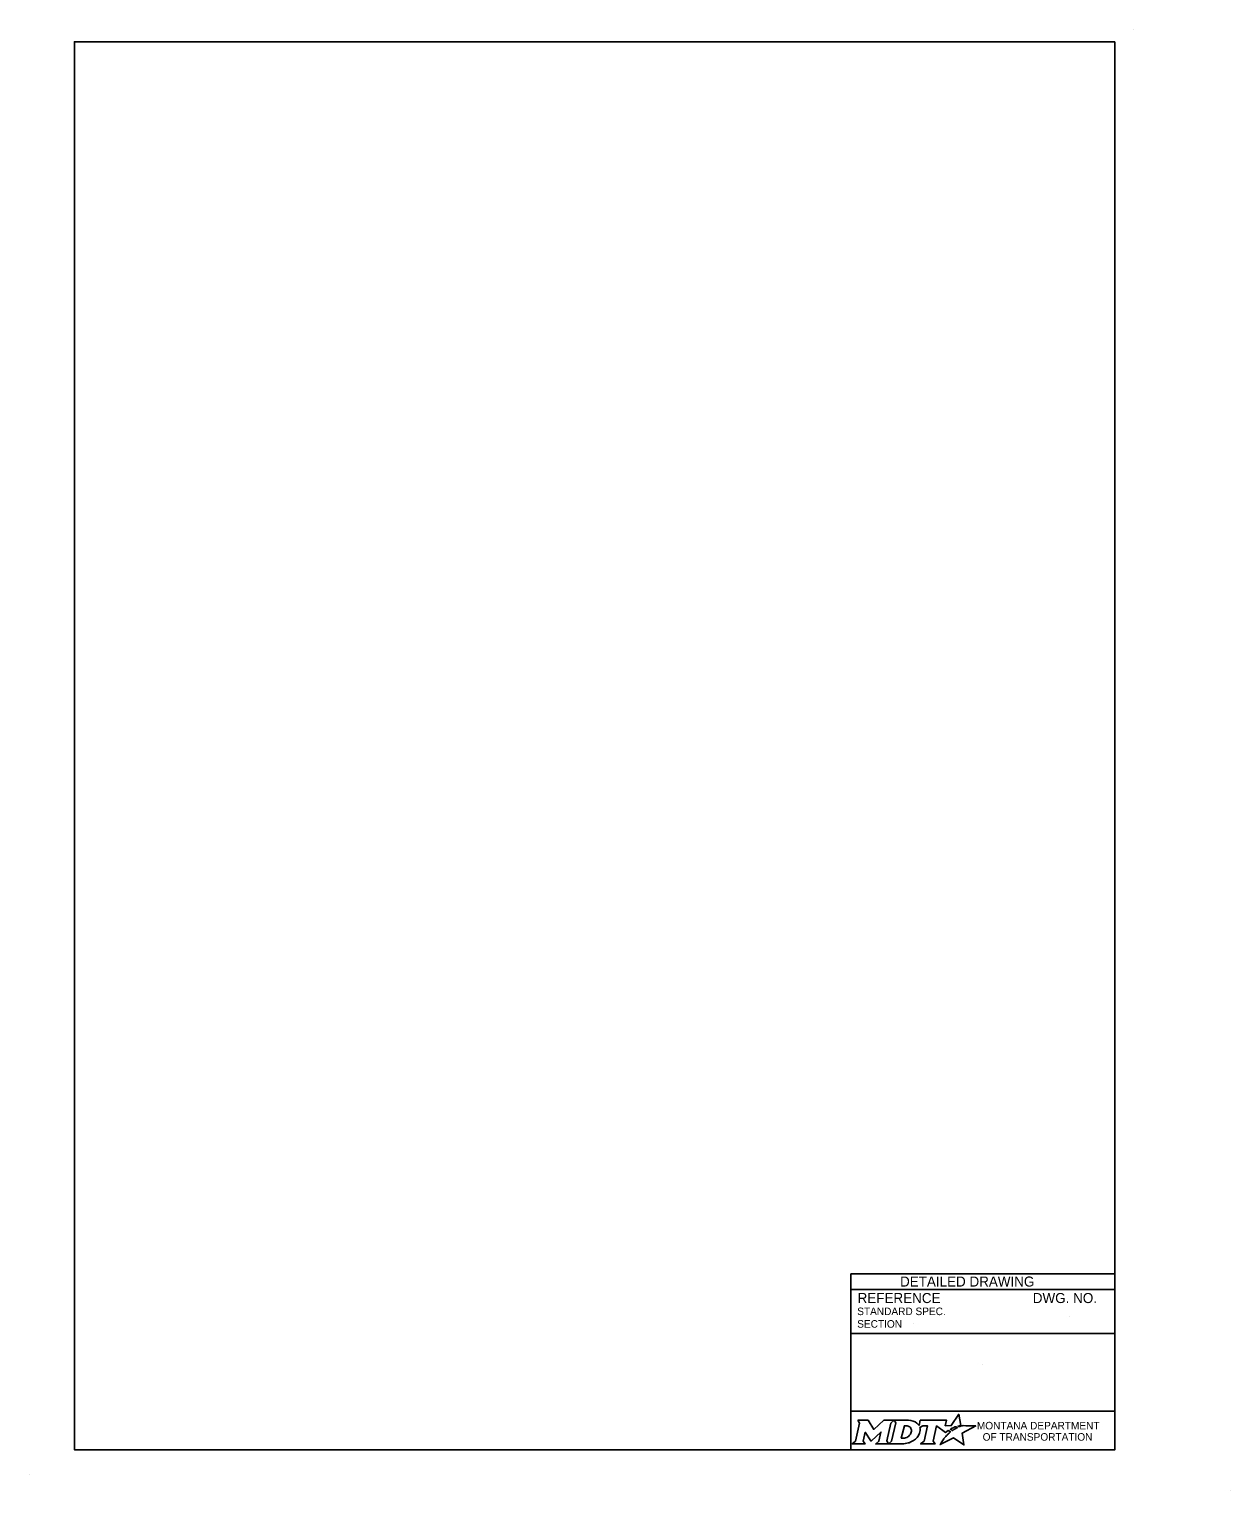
# Model space of a CAD drawing. Extents: x 49991.4 to 50021, y 49987.6 to 50011.4.
# Drawn here: x 49999.98 to 50009.54, y 49999.74 to 50011.36 of the extents above; entities that cross this region are included whole.
import ezdxf

# ---------------------------------------------------------------- set-up
doc = ezdxf.new("R2010")
doc.units = 0
doc.layers.add('Level 1', color=7, linetype='Continuous')
doc.layers.add('Level 2', color=7, linetype='Continuous')

msp = doc.modelspace()

# ---------------------------------------------------------------- linework, layer by layer
at = {"layer": 'Level 1'}
for p, q in [((50008.765, 50011.363), (50008.765, 50011.363)), ((49999.977, 49999.862), (49999.977, 49999.862)), ((50009.537, 49999.736), (50009.537, 49999.736))]:
    msp.add_line(p, q, dxfattribs=at)
msp.add_lwpolyline([(50008.615, 50011.263), (50000.336, 50011.263), (50000.336, 50000.062), (50008.615, 50000.062)], close=True, dxfattribs=at)
at = {"layer": 'Level 2'}
for p, q in [((50008.615, 50001.462), (50006.515, 50001.462)), ((50006.515, 50001.462), (50006.515, 50000.062)), ((50008.615, 50001.337), (50006.515, 50001.337)), ((50007.009, 50001.063), (50007.009, 50001.063)), ((50008.251, 50001.122), (50008.251, 50001.122)), ((50008.615, 50000.987), (50006.515, 50000.987)), ((50007.565, 50000.738), (50007.565, 50000.738)), ((50008.615, 50000.369), (50006.515, 50000.369))]:
    msp.add_line(p, q, dxfattribs=at)
for points in [[(50007.377, 50000.245), (50007.367, 50000.25), (50007.378, 50000.253), (50007.39, 50000.255), (50007.373, 50000.345), (50007.313, 50000.254), (50007.266, 50000.253), (50007.276, 50000.297), (50007.067, 50000.297), (50007.057, 50000.255), (50007.051, 50000.263)], [(50006.57, 50000.297), (50006.584, 50000.274), (50006.551, 50000.131), (50006.525, 50000.108), (50006.627, 50000.108), (50006.613, 50000.131), (50006.629, 50000.201), (50006.673, 50000.132), (50006.678, 50000.132), (50006.753, 50000.202), (50006.737, 50000.13), (50006.712, 50000.108), (50006.814, 50000.108), (50006.8, 50000.132), (50006.833, 50000.274)], [(50006.833, 50000.274), (50006.859, 50000.297), (50006.776, 50000.297), (50006.697, 50000.224), (50006.652, 50000.297), (50006.57, 50000.297)], [(50006.972, 50000.297), (50006.859, 50000.297), (50006.873, 50000.275), (50006.839, 50000.131), (50006.814, 50000.108), (50006.925, 50000.108)], [(50006.996, 50000.211), (50006.995, 50000.203), (50006.992, 50000.193), (50006.988, 50000.185), (50006.982, 50000.178), (50006.976, 50000.171), (50006.968, 50000.164), (50006.959, 50000.16), (50006.95, 50000.156), (50006.941, 50000.154), (50006.932, 50000.153), (50006.916, 50000.153), (50006.94, 50000.253), (50006.956, 50000.253), (50006.963, 50000.252), (50006.971, 50000.25), (50006.977, 50000.247), (50006.983, 50000.243), (50006.988, 50000.238), (50006.992, 50000.232), (50006.995, 50000.226), (50006.996, 50000.218), (50006.996, 50000.215), (50006.996, 50000.211)], [(50007.064, 50000.238), (50007.088, 50000.251), (50007.125, 50000.251), (50007.097, 50000.131), (50007.069, 50000.108), (50007.185, 50000.108), (50007.168, 50000.131), (50007.196, 50000.251), (50007.268, 50000.2), (50007.289, 50000.215), (50007.309, 50000.204)], [(50007.253, 50000.148), (50007.237, 50000.124), (50007.233, 50000.116), (50007.227, 50000.107), (50007.225, 50000.103), (50007.33, 50000.156), (50007.414, 50000.101), (50007.401, 50000.194), (50007.508, 50000.252), (50007.458, 50000.253), (50007.428, 50000.253), (50007.407, 50000.254), (50007.401, 50000.252), (50007.396, 50000.251), (50007.387, 50000.249), (50007.377, 50000.245)], [(50007.327, 50000.217), (50007.324, 50000.215), (50007.306, 50000.225), (50007.316, 50000.231), (50007.32, 50000.233), (50007.329, 50000.237), (50007.335, 50000.239), (50007.343, 50000.243), (50007.35, 50000.245), (50007.362, 50000.238), (50007.358, 50000.236), (50007.353, 50000.233), (50007.349, 50000.231), (50007.344, 50000.228), (50007.342, 50000.227), (50007.339, 50000.225), (50007.337, 50000.224), (50007.334, 50000.222), (50007.332, 50000.221), (50007.329, 50000.219), (50007.327, 50000.217)], [(50006.97, 50000.116), (50006.979, 50000.118), (50006.992, 50000.124), (50007.012, 50000.135)], [(50007.267, 50000.164), (50007.267, 50000.164)]]:
    msp.add_lwpolyline(points, dxfattribs=at)
for centre, radius, start, end in [((50006.995, 50000.219), 0.0709, 339.5329, 15.8582), ((50006.951, 50000.236), 0.118, 300.9103, 339.1383)]:
    msp.add_arc(centre, radius, start, end, dxfattribs=at)
for centre, major_axis, ratio, start_param, end_param in [((50006.97, 50000.25), (0.0834, -0.0037), 0.568097, 0.61298, 1.570796), ((50007.026, 50000.257), (0.0361, -0.0295), 0.469099, 1.225588, 1.570796), ((50006.925, 50000.257), (0, 0.148), 0.987302, 3.139398, 3.456847), ((50007.26, 50000.156), (-0.00694, -0.00806), 0.008222, 0, 3.137361), ((50007.276, 50000.174), (-0.0098, -0.0102), 0.016458, 3.141593, 6.279097), ((50007.297, 50000.194), (-0.0112, -0.0097), 0.021651, 3.157348, 6.283185)]:
    msp.add_ellipse(centre, major_axis=major_axis, ratio=ratio, start_param=start_param, end_param=end_param, dxfattribs=at)

# ---------------------------------------------------------------- texts
for s, height, p in [('DETAILED DRAWING', 0.0799, (50006.906, 50001.36)), ('REFERENCE', 0.08, (50006.568, 50001.229)), ('DWG. NO.', 0.08, (50007.962, 50001.229)), ('STANDARD SPEC.', 0.06, (50006.565, 50001.133)), ('SECTION', 0.06, (50006.565, 50001.033))]:
    msp.add_text(s, height=height, dxfattribs=at).set_placement(p)
for s, p in [('MONTANA DEPARTMENT', (50007.517, 50000.224)), ('OF TRANSPORTATION', (50007.563, 50000.134))]:
    msp.add_text(s, height=0.06, rotation=360, dxfattribs=at).set_placement(p)

doc.saveas('drawing.dxf')
